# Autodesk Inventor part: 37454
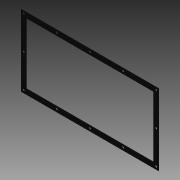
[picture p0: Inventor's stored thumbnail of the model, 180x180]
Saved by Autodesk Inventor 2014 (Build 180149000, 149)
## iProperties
Shininess: 20.0
Length Units: 11272
Angle Units: 11279
Time Units: 11290
Mass Units: 11286
Length Display Precision: 3
Angle Display Precision: 2
Company: Autodesk, Inc.
Created: 2002-06
Part Number: 37454
Material: Silicone
Description: GASKET
Document SubType Name: Modeling
Designer: Autodesk, Inc.
Density: 1.25 g/cm^3
Mass: 195.098 g
Surface Area: 1122.28 cm^2
Volume: 156.079 cm^3
Appearance: Black Vinyl (texture)
Density: 0.0
Volumn: 0.0
Area: 0.0
PropertySet Name: Model Information
Control State: 0
Master: False
Checked Out: False
Last Check In By: JT
Last Check In Date: 2003-06-20
Title: GASKET
Author: Autodesk, Inc.
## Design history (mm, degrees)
sketch "Sketch1"
  geometry: L1 (-342.9, 177.8)-(342.9, 177.8); L2 (342.9, 177.8)-(342.9, -177.8); L3 (342.9, -177.8)-(-342.9, -177.8); L4 (-342.9, -177.8)-(-342.9, 177.8); L5 (0, 177.8)-(0, -177.8); L6 (0, 0)-(342.9, 0); L7 (317.5, 152.4)-(-317.5, 152.4); L8 (-317.5, 152.4)-(-317.5, -152.4); L9 (-317.5, -152.4)-(317.5, -152.4); L10 (317.5, -152.4)-(317.5, 152.4); 1 further point
  constraints: 20 end point, 4 midpoint, 4 parallel, 2 perpendicular, 1 coincident, 1 horizontal, 3 other
  dimensions: "d3" = 355.6 distance of L3.end L1.start; "d4" = 685.8 distance of L1.start L1.end; "d5" = 25.4 distance between parallel lines of L4 L8
extrude "Extrusion2" new body sketch "Sketch1" distance "d6" = 3.175; taper "d7" = 0 deg
sketch "Sketch2"
  geometry: L1 (-342.9, 177.8)-(342.9, 177.8) reference; L2 (-342.9, -177.8)-(-342.9, 177.8) reference; L3 (342.9, -177.8)-(-342.9, -177.8) reference; L4 (342.9, 177.8)-(342.9, -177.8) reference; 13 further points
  constraints: 10 horizontal alignment, 8 vertical alignment
  dimensions: "d8" = 12.7 distance from line of L2 point (-330.2, 165.1); "d9" = 12.7 distance from line of L1 point (-330.2, 165.1); "d10" = 12.7 distance from line of L3 point (-330.2, -165.1); "d11" = 12.7 distance from line of L4 point (330.2, -165.1); "d21" = 165.1 distance of point (-165.1, 165.1) point (-330.2, 165.1); "d22" = 165.1 distance of point (330.2, 165.1) point (165.1, 165.1); "d23" = 165.1 distance of point (0, 165.1) point (165.1, 165.1) (derived); "d24" = 165.1 distance of point (-330.2, -165.1) point (-330.2, 0) (derived); "d25" = 165.1 distance of point (-330.2, 0) point (-330.2, 165.1) (derived)
hole "Hole1" sketch "Sketch2" at (-330.2, 165.1), (-330.2, 0), (-330.2, -165.1), (-165.1, -165.1), (0, -165.1), (165.1, -165.1), (330.2, -165.1), (330.2, 0), (330.2, 165.1), (165.1, 165.1), (0, 165.1), (-165.1, 165.1) diameter "d14" = 11.1125; stored, may be unused: countersink angle "d18" = 82 deg, drill point angle "d20" = 118 deg; dims "d15" = 12.7, "d16" = 9.525, "d17" = 6.35, "d19" = 19.05
body "Solid1"
